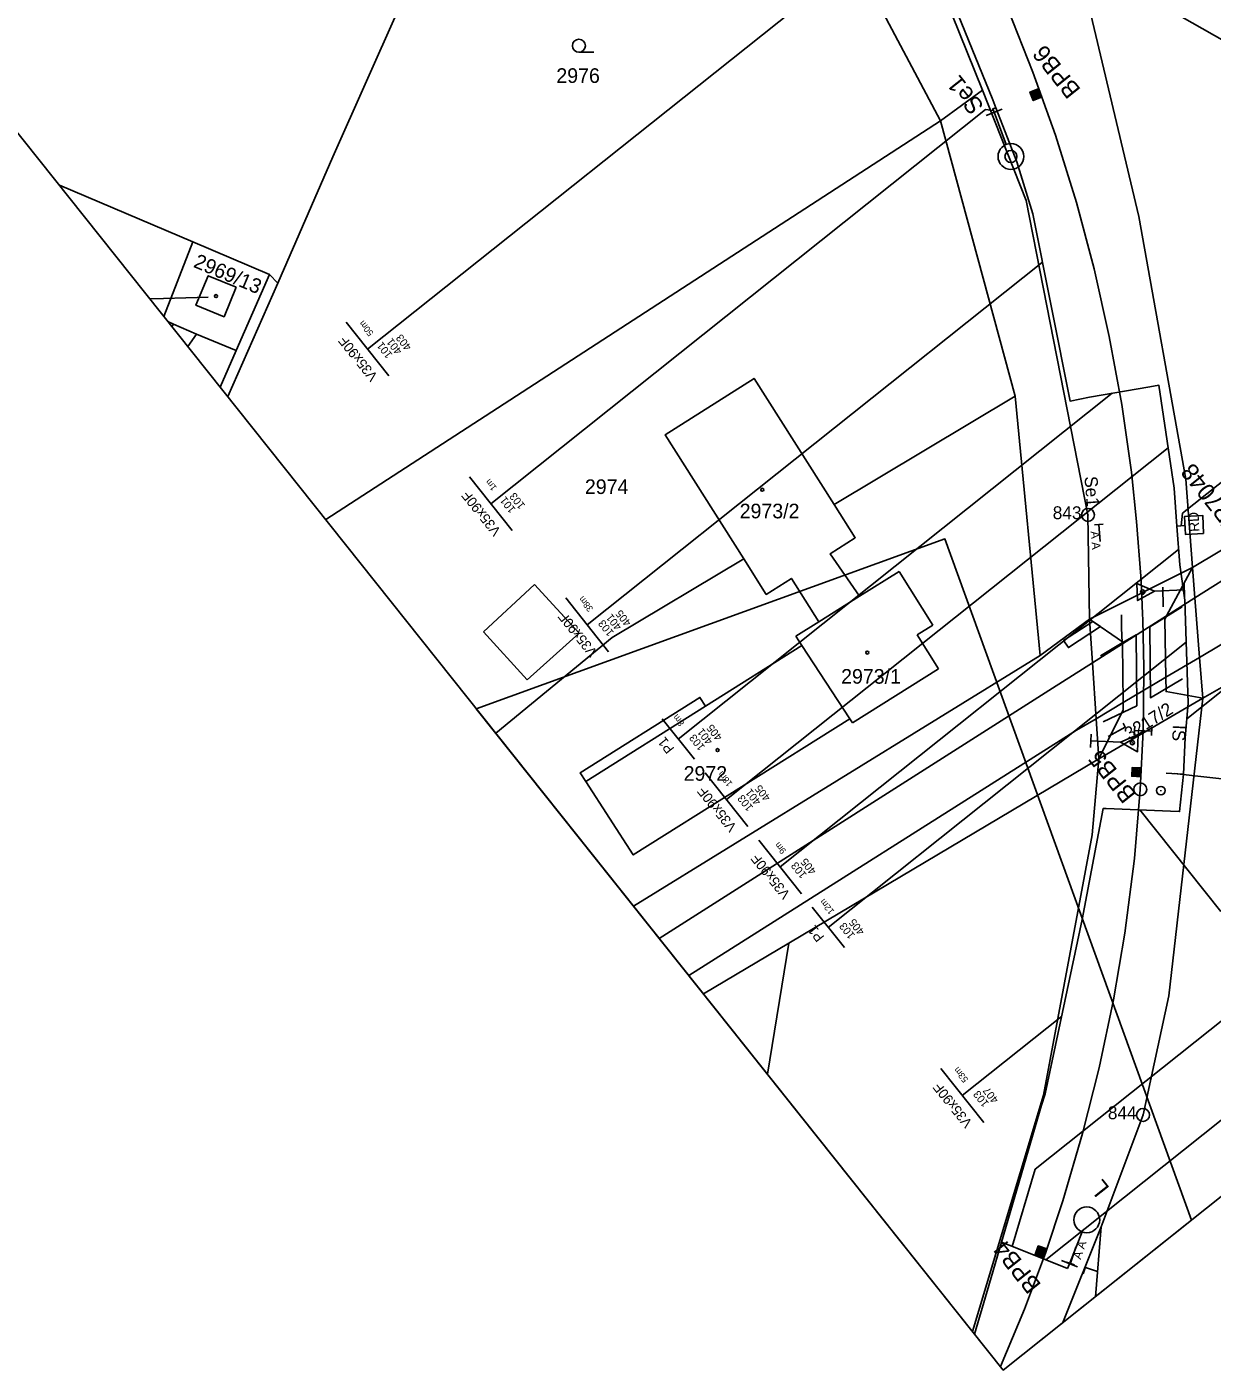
# Model space of a CAD drawing. Extents: x -620412 to -620034, y -1122986 to -1122565.
# Drawn here: x -620264 to -620126.1, y -1122986.3 to -1122830 of the extents above; entities that cross this region are included whole.
import ezdxf

# ---------------------------------------------------------------- set-up
doc = ezdxf.new("R2010")
doc.units = 0
for name, color, linetype in [('HranDP', 7, 'Continuous'), ('Hranice parcel', 7, 'Continuous'), ('Parcelní čísla', 7, 'Continuous'), ('Pop  PČ popisy', 7, 'Continuous'), ('Rámečky', 7, 'Continuous'), ('Rámečky-tisk', 7, 'Continuous'), ('Vnitřní kresba', 7, 'Continuous'), ('Vrstva 1', 7, 'Continuous'), ('Vrstva 19', 7, 'Continuous'), ('Vrstva 2', 7, 'Continuous'), ('Vrstva 3', 7, 'Continuous'), ('Vrstva 33', 7, 'Continuous'), ('Vrstva 4', 7, 'Continuous'), ('Vrstva 51', 7, 'Continuous'), ('Vrstva 6', 7, 'Continuous'), ('Vrstva 7', 7, 'Continuous'), ('Věcná břemena k části', 7, 'Continuous'), ('Značky bodu BP', 7, 'Continuous'), ('Značky budov', 7, 'Continuous'), ('Značky kultur', 7, 'Continuous')]:
    doc.layers.add(name, color=color, linetype=linetype)

msp = doc.modelspace()

# ---------------------------------------------------------------- linework, layer by layer
at = {"layer": 'HranDP'}
for points in [[(-620152.84, -1122837.4), (-620159.98, -1122819.68), (-620173.68, -1122796.12), (-620181.92, -1122785.4)], [(-620143.18, -1122816.17), (-620134.66, -1122852.11), (-620129.18, -1122882.66), (-620128.4, -1122892.9)], [(-620140.38, -1122898.92), (-620140.56, -1122886.8), (-620147.76, -1122850.22), (-620152.84, -1122837.4)], [(-620128.4, -1122892.9), (-620131.42, -1122898.55), (-620131.63, -1122898.95), (-620131.51, -1122905.69)], [(-620140.38, -1122898.92), (-620136.53, -1122901.57), (-620136.53, -1122901.79), (-620136.48, -1122908.63), (-620136.47, -1122909.48), (-620139.31, -1122915.18)], [(-620131.51, -1122905.69), (-620131.48, -1122907.34), (-620127.22, -1122908.12)], [(-620139.01, -1122969.61), (-620134.15, -1122956.58), (-620131.17, -1122942.74), (-620127.22, -1122908.12)], [(-620139.31, -1122915.18), (-620140.08, -1122924.01), (-620145.74, -1122954.29), (-620154, -1122981.77)], [(-620139.01, -1122969.61), (-620143.47, -1122980.73)]]:
    msp.add_lwpolyline(points, dxfattribs=at)
at = {"layer": 'Hranice parcel'}
for p, q in [((-620244.68, -1122855.06), (-620260.19, -1122848.46)), ((-620244.68, -1122855.06), (-620235.77, -1122858.86)), ((-620234.78, -1122859.86), (-620235.77, -1122858.86)), ((-620140.38, -1122898.92), (-620128.4, -1122892.9)), ((-620105.32, -1122895.5), (-620127.22, -1122908.12)), ((-620146.13, -1122903.17), (-620140.38, -1122898.92)), ((-620193.4, -1122932.31), (-620146.13, -1122903.17)), ((-620127.22, -1122908.12), (-620139.31, -1122915.18)), ((-620139.31, -1122915.18), (-620175.35, -1122936.6)), ((-620139.69, -1122977.72), (-620139.01, -1122969.61))]:
    msp.add_line(p, q, dxfattribs=at)
for points in [[(-620234.78, -1122859.86), (-620228.39, -1122845.14), (-620201.6, -1122784.9)], [(-620152.84, -1122837.4), (-620159.98, -1122819.68), (-620173.68, -1122796.12), (-620181.92, -1122785.4)], [(-620143.18, -1122816.17), (-620134.66, -1122852.11), (-620129.18, -1122882.66), (-620128.4, -1122892.9)], [(-620080.86, -1122856.55), (-620132.47, -1122827.27), (-620136.72, -1122822.9), (-620143.18, -1122816.17)], [(-620152.84, -1122837.4), (-620157.72, -1122840.99), (-620229.22, -1122887.34)], [(-620140.38, -1122898.92), (-620140.56, -1122886.8), (-620147.76, -1122850.22), (-620152.84, -1122837.4)], [(-620248.05, -1122863.71), (-620244.68, -1122855.06)], [(-620128.4, -1122892.9), (-620078.79, -1122863.28), (-620080.86, -1122856.55)], [(-620235.77, -1122858.86), (-620239.62, -1122867.69), (-620244.23, -1122865.77), (-620246.9, -1122864.61), (-620247.56, -1122864.32)], [(-620239.62, -1122860.31), (-620241.03, -1122863.75), (-620244.32, -1122862.42), (-620242.88, -1122858.98), (-620239.62, -1122860.31)], [(-620240.61, -1122873.04), (-620234.78, -1122859.86)], [(-620170.07, -1122885.6), (-620179.4, -1122870.92), (-620189.75, -1122877.5), (-620180.6, -1122891.9)], [(-620146.13, -1122903.17), (-620149.02, -1122872.99), (-620170.07, -1122885.6)], [(-620170.07, -1122885.6), (-620167.62, -1122889.46), (-620170.53, -1122891.31), (-620167.12, -1122896.26), (-620171.85, -1122899.25), (-620175.05, -1122894.19), (-620177.97, -1122896.04), (-620180.6, -1122891.9)], [(-620180.6, -1122891.9), (-620195.9, -1122901.07), (-620209.42, -1122912.19)], [(-620128.4, -1122892.9), (-620131.42, -1122898.55), (-620131.63, -1122898.95), (-620131.51, -1122905.69)], [(-620140.38, -1122898.92), (-620136.53, -1122901.57), (-620136.53, -1122901.79), (-620136.48, -1122908.63), (-620136.47, -1122909.48), (-620139.31, -1122915.18)], [(-620198.98, -1122917.79), (-620193.45, -1122926.35), (-620168.27, -1122910.5), (-620173.85, -1122901.99), (-620185.06, -1122909.04), (-620185.7, -1122908.03), (-620199.62, -1122916.78), (-620198.98, -1122917.79)], [(-620131.51, -1122905.69), (-620131.48, -1122907.34), (-620127.22, -1122908.12)], [(-620139.01, -1122969.61), (-620134.15, -1122956.58), (-620131.17, -1122942.74), (-620127.22, -1122908.12)], [(-620139.31, -1122915.18), (-620140.08, -1122924.01), (-620145.74, -1122954.29), (-620154, -1122981.77)], [(-620175.35, -1122936.6), (-620185.28, -1122942.5)], [(-620175.35, -1122936.6), (-620177.83, -1122951.85)], [(-620139.01, -1122969.61), (-620143.47, -1122980.73)]]:
    msp.add_lwpolyline(points, dxfattribs=at)
at = {"layer": 'Pop  PČ popisy'}
for p, q in [((-620248.09, -1122861.62), (-620249.67, -1122861.68)), ((-620242.88, -1122861.46), (-620248.09, -1122861.62))]:
    msp.add_line(p, q, dxfattribs=at)
at = {"layer": 'Rámečky'}
for points in [[(-620128.51, -1122968.81), (-620157.19, -1122889.6), (-620211.7, -1122909.34)], [(-620211.7, -1122909.34), (-620150.41, -1122986.26), (-620128.51, -1122968.81)]]:
    msp.add_lwpolyline(points, dxfattribs=at)
at = {"layer": 'Rámečky-tisk'}
for points in [[(-620412.11, -1122657.76), (-620150.41, -1122986.26), (-620034.26, -1122893.74), (-620295.96, -1122565.23)], [(-620128.51, -1122968.81), (-620157.19, -1122889.6), (-620211.7, -1122909.34)], [(-620211.7, -1122909.34), (-620150.41, -1122986.26), (-620128.51, -1122968.81)]]:
    msp.add_lwpolyline(points, dxfattribs=at)
at = {"layer": 'Vnitřní kresba'}
for p, q in [((-620185.65, -1122788.07), (-620157.72, -1122840.99)), ((-620149.02, -1122872.99), (-620157.72, -1122840.99)), ((-620246.9, -1122864.61), (-620247.1, -1122864.9)), ((-620245.24, -1122867.23), (-620244.23, -1122865.77)), ((-620239.62, -1122867.69), (-620241.48, -1122871.95)), ((-620119.37, -1122890.92), (-620128.12, -1122896.46)), ((-620162.51, -1122893.37), (-620167.12, -1122896.26)), ((-620158.59, -1122899.61), (-620162.51, -1122893.37)), ((-620128.4, -1122892.9), (-620128.12, -1122896.46)), ((-620210.87, -1122900.4), (-620204.92, -1122894.91)), ((-620204.92, -1122894.91), (-620199.73, -1122900.55)), ((-620128.12, -1122896.46), (-620131.42, -1122898.55)), ((-620128.12, -1122896.46), (-620127.59, -1122903.37)), ((-620115.07, -1122895.95), (-620127.59, -1122903.37)), ((-620171.85, -1122899.25), (-620174.52, -1122900.92)), ((-620160.44, -1122900.76), (-620158.59, -1122899.61)), ((-620140.38, -1122898.92), (-620140.04, -1122904.01)), ((-620131.42, -1122898.55), (-620136.53, -1122901.79)), ((-620205.8, -1122906), (-620210.87, -1122900.4)), ((-620199.73, -1122900.55), (-620205.8, -1122906)), ((-620174.52, -1122900.92), (-620173.85, -1122901.99)), ((-620157.94, -1122904.69), (-620160.44, -1122900.76)), ((-620136.53, -1122901.79), (-620140.04, -1122904.01)), ((-620167.95, -1122911), (-620157.94, -1122904.69)), ((-620140.04, -1122904.01), (-620144.7, -1122906.96)), ((-620140.04, -1122904.01), (-620139.62, -1122910.5)), ((-620127.59, -1122903.37), (-620131.51, -1122905.69)), ((-620127.59, -1122903.37), (-620127.22, -1122908.12)), ((-620131.51, -1122905.69), (-620136.48, -1122908.63)), ((-620144.7, -1122906.96), (-620190.42, -1122936.05)), ((-620185.06, -1122909.04), (-620198.98, -1122917.79)), ((-620136.48, -1122908.63), (-620139.62, -1122910.5)), ((-620168.27, -1122910.5), (-620167.95, -1122911)), ((-620139.62, -1122910.5), (-620141.9, -1122911.85)), ((-620139.62, -1122910.5), (-620139.31, -1122915.18)), ((-620141.9, -1122911.85), (-620186.97, -1122940.37))]:
    msp.add_line(p, q, dxfattribs=at)
at = {"layer": 'Vrstva 1'}
for p, q in [((-620133.37, -1122871.92), (-620140.39, -1122873.11)), ((-620129.27, -1122888.02), (-620130.22, -1122888.11)), ((-620128.92, -1122908.69), (-620129.3, -1122896.72)), ((-620131.45, -1122916.84), (-620129.47, -1122916.94)), ((-620130.97, -1122921.27), (-620138.43, -1122920.94)), ((-620148.83, -1122972.09), (-620150.63, -1122971.37)), ((-620142.94, -1122974.46), (-620148.83, -1122972.09)), ((-620142.71, -1122973.89), (-620142.94, -1122974.46))]:
    msp.add_line(p, q, dxfattribs=at)
for points in [[(-620151.28, -1122839.45), (-620151.64, -1122838.53), (-620158.91, -1122820.61), (-620164.59, -1122810.94), (-620173.13, -1122796.4), (-620173.84, -1122795.49)], [(-620149.89, -1122827.96), (-620146.96, -1122835.3), (-620144.33, -1122842.64), (-620141.9, -1122850.48), (-620139.85, -1122858.17), (-620138.09, -1122866.06), (-620136.62, -1122873.96), (-620135.51, -1122881.84), (-620134.9, -1122887.57), (-620134.42, -1122893.91), (-620134.34, -1122895.32), (-620134.21, -1122898.3), (-620134.18, -1122899.02), (-620134.08, -1122904.54), (-620134.09, -1122909), (-620134.14, -1122911.92), (-620134.48, -1122918.72), (-620135.16, -1122926.76), (-620136.29, -1122935.46), (-620137.6, -1122943.19), (-620139.25, -1122951.1), (-620141.18, -1122958.74), (-620143.49, -1122966.59), (-620145.52, -1122972.66), (-620147.96, -1122979.17), (-620150.73, -1122985.86)], [(-620151.28, -1122839.45), (-620151.63, -1122839.59), (-620151.49, -1122839.98)], [(-620140.39, -1122873.11), (-620142.65, -1122873.56), (-620146.97, -1122851.79), (-620148.85, -1122845.74), (-620151.28, -1122839.45)], [(-620130.22, -1122888.11), (-620130.54, -1122883.68), (-620132.31, -1122871.72), (-620133.37, -1122871.92)], [(-620129.3, -1122896.72), (-620129.88, -1122892.6), (-620129.88, -1122892.6), (-620130.22, -1122888.11)], [(-620129.47, -1122916.94), (-620129.26, -1122912.72), (-620129.26, -1122912.72), (-620128.92, -1122908.69)], [(-620130.97, -1122921.27), (-620129.91, -1122921.31), (-620129.47, -1122916.94)], [(-620150.63, -1122971.37), (-620145.98, -1122955.43), (-620145.54, -1122954.13), (-620141.24, -1122933.85), (-620138.78, -1122920.93), (-620138.43, -1122920.94)], [(-620153.75, -1122982.08), (-620152.3, -1122977.09), (-620150.63, -1122971.37)]]:
    msp.add_lwpolyline(points, dxfattribs=at)
at = {"layer": 'Vrstva 19'}
msp.add_line((-620131.87, -1122895.21), (-620131.8, -1122897.49), dxfattribs=at)
for points in [[(-620139.12, -1122903.19), (-620136.58, -1122901.68), (-620136.67, -1122899.95), (-620136.66, -1122899.92), (-620136.68, -1122898.42)], [(-620136.48, -1122911.01), (-620136.23, -1122911.48), (-620138.22, -1122912.56)]]:
    msp.add_lwpolyline(points, dxfattribs=at)
at = {"layer": 'Vrstva 2'}
for p, q in [((-620146.92, -1122837.47), (-620146.12, -1122837.82)), ((-620146.75, -1122837.4), (-620146.19, -1122837.64)), ((-620146.58, -1122837.33), (-620146.26, -1122837.47)), ((-620146.4, -1122837.27), (-620146.33, -1122837.3)), ((-620147.28, -1122837.75), (-620146.07, -1122838.27)), ((-620147.26, -1122837.61), (-620145.98, -1122838.16)), ((-620147.21, -1122837.92), (-620146.25, -1122838.33)), ((-620147.14, -1122838.09), (-620146.42, -1122838.4)), ((-620147.09, -1122837.54), (-620146.05, -1122837.99)), ((-620147.07, -1122838.26), (-620146.59, -1122838.47)), ((-620147, -1122838.44), (-620146.76, -1122838.54)), ((-620150.55, -1122839.62), (-620152.42, -1122840.34)), ((-620150.06, -1122843.72), (-620151.49, -1122839.98)), ((-620135.46, -1122917.02), (-620135.28, -1122917.21)), ((-620135.45, -1122916.83), (-620135.1, -1122917.22)), ((-620135.44, -1122916.46), (-620134.73, -1122917.24)), ((-620135.44, -1122916.65), (-620134.91, -1122917.23)), ((-620135.43, -1122916.28), (-620134.54, -1122917.24)), ((-620135.36, -1122916.16), (-620134.42, -1122917.19)), ((-620135.18, -1122916.17), (-620134.41, -1122917)), ((-620134.99, -1122916.17), (-620134.4, -1122916.81)), ((-620134.8, -1122916.18), (-620134.39, -1122916.63)), ((-620134.62, -1122916.19), (-620134.38, -1122916.44)), ((-620134.43, -1122916.2), (-620134.38, -1122916.26)), ((-620141.25, -1122970.17), (-620142.71, -1122973.89)), ((-620146.28, -1122971.83), (-620145.68, -1122973.09)), ((-620146.62, -1122972.63), (-620146.51, -1122972.86)), ((-620146.56, -1122972.45), (-620146.34, -1122972.92)), ((-620146.5, -1122972.28), (-620146.16, -1122972.98)), ((-620146.44, -1122972.1), (-620145.99, -1122973.05)), ((-620146.38, -1122971.93), (-620145.81, -1122973.11)), ((-620146.1, -1122971.89), (-620145.61, -1122972.92)), ((-620145.93, -1122971.95), (-620145.55, -1122972.74)), ((-620145.75, -1122972.02), (-620145.49, -1122972.57)), ((-620145.58, -1122972.08), (-620145.43, -1122972.39)), ((-620145.4, -1122972.14), (-620145.37, -1122972.22)), ((-620143.65, -1122973.53), (-620141.78, -1122974.26))]:
    msp.add_line(p, q, dxfattribs=at)
for points in [[(-620146.35, -1122837.24), (-620145.96, -1122838.22), (-620146.93, -1122838.61), (-620147.32, -1122837.63)], [(-620146.35, -1122837.24), (-620145.96, -1122838.22), (-620146.93, -1122838.61), (-620147.32, -1122837.63)], [(-620127.12, -1122888.96), (-620127.22, -1122886.86), (-620129.32, -1122886.97), (-620129.22, -1122889.07)], [(-620134.37, -1122916.2), (-620134.42, -1122917.25), (-620135.47, -1122917.2), (-620135.42, -1122916.16)], [(-620134.37, -1122916.2), (-620134.42, -1122917.25), (-620135.47, -1122917.2), (-620135.42, -1122916.16)], [(-620145.35, -1122972.16), (-620145.7, -1122973.15), (-620146.69, -1122972.8), (-620146.34, -1122971.81)], [(-620145.35, -1122972.16), (-620145.7, -1122973.15), (-620146.69, -1122972.8), (-620146.34, -1122971.81)]]:
    msp.add_lwpolyline(points, close=True, dxfattribs=at)
for centre, radius in [((-620149.52, -1122845.12), 1.5), ((-620149.52, -1122845.12), 0.7), ((-620140.7, -1122968.78), 1.5)]:
    msp.add_circle(centre, radius, dxfattribs=at)
at = {"layer": 'Vrstva 3'}
for p, q in [((-620135.12, -1122911.37), (-620135.17, -1122912.37)), ((-620133.14, -1122911.97), (-620135.14, -1122911.87)), ((-620133.12, -1122911.47), (-620133.17, -1122912.47))]:
    msp.add_line(p, q, dxfattribs=at)
at = {"layer": 'Vrstva 33'}
for p, q in [((-620161, -1122817.05), (-620224.35, -1122867.51)), ((-620152.47, -1122839.66), (-620210.02, -1122885.5)), ((-620152.47, -1122839.66), (-620151.57, -1122839.76)), ((-620129.55, -1122886.6), (-620085.16, -1122851.24)), ((-620145.85, -1122857.4), (-620198.8, -1122899.58)), ((-620226.84, -1122864.38), (-620221.86, -1122870.64)), ((-620129.07, -1122910.51), (-620073.32, -1122866.1)), ((-620137.73, -1122872.66), (-620188.21, -1122912.87)), ((-620131.24, -1122878.99), (-620182.6, -1122919.91)), ((-620212.51, -1122882.37), (-620207.52, -1122888.63)), ((-620129.55, -1122886.6), (-620129.71, -1122888.06)), ((-620146.7, -1122962.91), (-620054.63, -1122889.57)), ((-620130.02, -1122890.81), (-620176.37, -1122927.73)), ((-620201.29, -1122896.45), (-620196.31, -1122902.71)), ((-620145.47, -1122973.44), (-620049.02, -1122896.6)), ((-620129.15, -1122901.62), (-620170.76, -1122934.77)), ((-620190.08, -1122910.53), (-620186.34, -1122915.22)), ((-620185.09, -1122916.78), (-620180.11, -1122923.04)), ((-620130.52, -1122916.89), (-620122.21, -1122917.83)), ((-620134.54, -1122921.11), (-620125.12, -1122932.93)), ((-620178.86, -1122924.61), (-620173.88, -1122930.86)), ((-620172.63, -1122932.43), (-620168.89, -1122937.12)), ((-620143.63, -1122945.12), (-620155.19, -1122954.33)), ((-620157.68, -1122951.2), (-620152.69, -1122957.46)), ((-620146.7, -1122962.91), (-620149.37, -1122971.88))]:
    msp.add_line(p, q, dxfattribs=at)
at = {"layer": 'Vrstva 4'}
for p, q in [((-620129.33, -1122896.31), (-620129.39, -1122894.76)), ((-620134.02, -1122895.95), (-620134.37, -1122895.61)), ((-620140.19, -1122912.29), (-620140.28, -1122913.84)), ((-620135.56, -1122913.09), (-620135.23, -1122913.46))]:
    msp.add_line(p, q, dxfattribs=at)
for points in [[(-620129.36, -1122895.53), (-620132.83, -1122895.69), (-620134.79, -1122896.76), (-620134.89, -1122894.77), (-620132.83, -1122895.69)], [(-620134.18, -1122899.02), (-620134.08, -1122904.54), (-620134.09, -1122909)], [(-620140.23, -1122913.07), (-620136.76, -1122913.24), (-620134.71, -1122912.35), (-620134.8, -1122914.35), (-620136.76, -1122913.24)]]:
    msp.add_lwpolyline(points, dxfattribs=at)
for centre in [(-620134.19, -1122895.78), (-620135.4, -1122913.28)]:
    msp.add_circle(centre, 0.248, dxfattribs=at)
at = {"layer": 'Vrstva 51'}
for points in [[(-620129.62, -1122897.5), (-620133.36, -1122899.81), (-620133.29, -1122908.06), (-620129.57, -1122905.87)], [(-620138.79, -1122910.87), (-620134.88, -1122909), (-620134.94, -1122900.75), (-620136.58, -1122901.68)]]:
    msp.add_lwpolyline(points, dxfattribs=at)
at = {"layer": 'Vrstva 6'}
for p, q in [((-620138.81, -1122887.87), (-620139.8, -1122887.95)), ((-620139.16, -1122889.88), (-620139.31, -1122887.91)), ((-620141.96, -1122971.97), (-620142.59, -1122973.84)), ((-620143.06, -1122973.69), (-620142.12, -1122974))]:
    msp.add_line(p, q, dxfattribs=at)
at = {"layer": 'Vrstva 7'}
msp.add_line((-620132.07, -1122918.82), (-620132.08, -1122918.92), dxfattribs=at)
for centre, radius in [((-620134.48, -1122918.72), 0.75), ((-620132.08, -1122918.87), 0.5)]:
    msp.add_circle(centre, radius, dxfattribs=at)
at = {"layer": 'Věcná břemena k části'}
msp.add_lwpolyline([(-620139.12, -1122899.79), (-620140.01, -1122899.18), (-620143.39, -1122901.4), (-620142.84, -1122902.23)], close=True, dxfattribs=at)
at = {"layer": 'Značky bodu BP'}
for centre, radius in [((-620140.56, -1122886.8), 0.75), ((-620140.56, -1122886.8), 0.03), ((-620134.15, -1122956.58), 0.75), ((-620134.15, -1122956.58), 0.03)]:
    msp.add_circle(centre, radius, dxfattribs=at)
at = {"layer": 'Značky budov'}
for centre in [(-620241.97, -1122861.36), (-620178.44, -1122883.88), (-620166.23, -1122902.81), (-620183.64, -1122914.16)]:
    msp.add_circle(centre, 0.175, dxfattribs=at)
at = {"layer": 'Značky kultur'}
msp.add_line((-620199.77, -1122832.99), (-620198.02, -1122832.99), dxfattribs=at)
msp.add_circle((-620199.77, -1122832.24), 0.75, dxfattribs=at)

# ---------------------------------------------------------------- texts
at = {"layer": 'Parcelní čísla'}
for s, p in [('2976', (-620202.39, -1122836.56)), ('2974', (-620199.07, -1122884.37)), ('2973/2', (-620181.07, -1122887.2)), ('2973/1', (-620169.27, -1122906.43)), ('2972', (-620187.59, -1122917.72))]:
    msp.add_text(s, height=1.7, dxfattribs=at).set_placement(p)
for s, height, rotation, p in [('2969/13', 1.7, 337, (-620244.7, -1122857.94)), ('3217/2', 1.5, 32, (-620135.73, -1122913.04))]:
    msp.add_text(s, height=height, rotation=rotation, dxfattribs=at).set_placement(p)
at = {"layer": 'Vrstva 2'}
msp.add_text('RD', height=1.2, rotation=93.0505, dxfattribs=at).set_placement((-620127.58, -1122888.74))
at = {"layer": 'Vrstva 3'}
for s, height, rotation, p in [('BPB6', 2, 128.542, (-620141.32, -1122837.34)), ('Se1', 2, 128.542, (-620152.57, -1122839.22)), ('B1/P7048', 2, 128.542, (-620121.02, -1122889.81)), ('IS', 1.5, 267.1804, (-620130.68, -1122911.19)), ('BPB5', 2, 128.542, (-620134.84, -1122919.29)), ('L', 2, 128.542, (-620137.97, -1122965.09)), ('BPB4', 2, 128.542, (-620145.92, -1122976.33))]:
    msp.add_text(s, height=height, rotation=rotation, dxfattribs=at).set_placement(p)
at = {"layer": 'Vrstva 33'}
for s, height, p in [('50m', 0.75, (-620223.6, -1122865.64)), ('V35x90F', 1.15, (-620223.1, -1122870.68)), ('101', 0.9, (-620221.4, -1122868.16)), ('401', 0.9, (-620220.28, -1122867.72)), ('403', 0.9, (-620219.17, -1122867.26)), ('1m', 0.75, (-620209.27, -1122883.63)), ('V35x90F', 1.15, (-620208.77, -1122888.67)), ('103', 0.9, (-620205.97, -1122885.69)), ('101', 0.9, (-620207.07, -1122886.15)), ('38m', 0.75, (-620198.06, -1122897.7)), ('V35x90F', 1.15, (-620197.55, -1122902.75)), ('401', 0.9, (-620194.73, -1122899.79)), ('405', 0.9, (-620193.63, -1122899.33)), ('103', 0.9, (-620195.65, -1122900.48)), ('8m', 0.75, (-620187.46, -1122911)), ('103', 0.9, (-620185.06, -1122913.78)), ('401', 0.9, (-620184.14, -1122913.09)), ('405', 0.9, (-620183.03, -1122912.63)), ('P1', 1.15, (-620188.61, -1122913.98)), ('18m', 0.75, (-620181.86, -1122918.04)), ('V35x90F', 1.15, (-620181.35, -1122923.08)), ('401', 0.9, (-620178.53, -1122920.13)), ('405', 0.9, (-620177.43, -1122919.67)), ('103', 0.9, (-620179.45, -1122920.82)), ('9m', 0.75, (-620175.62, -1122925.86)), ('V35x90F', 1.15, (-620175.12, -1122930.9)), ('103', 0.9, (-620173.22, -1122928.64)), ('405', 0.9, (-620172.1, -1122928.2)), ('12m', 0.75, (-620170.02, -1122932.9)), ('103', 0.9, (-620167.61, -1122935.68)), ('405', 0.9, (-620166.49, -1122935.24)), ('P1', 1.15, (-620171.16, -1122935.88)), ('53m', 0.75, (-620154.44, -1122952.45)), ('V35x90F', 1.15, (-620153.94, -1122957.5)), ('103', 0.9, (-620152.03, -1122955.23)), ('407', 0.9, (-620150.9, -1122954.81))]:
    msp.add_text(s, height=height, rotation=128.542, dxfattribs=at).set_placement(p)
at = {"layer": 'Vrstva 6'}
for s, height, rotation, p in [('Se1', 1.5, 274.313, (-620140.97, -1122882.35)), ('  A A ', 1, 274.313, (-620140.3, -1122887.98)), ('  A A ', 1, 71.5027, (-620141.64, -1122974.16)), ('L', 1.5, 251.5027, (-620140.85, -1122974.05))]:
    msp.add_text(s, height=height, rotation=rotation, dxfattribs=at).set_placement(p)
at = {"layer": 'Značky bodu BP'}
for s, p in [('843', (-620144.66, -1122887.3)), ('844', (-620138.25, -1122957.08))]:
    msp.add_text(s, height=1.5, dxfattribs=at).set_placement(p)

doc.saveas('drawing.dxf')
